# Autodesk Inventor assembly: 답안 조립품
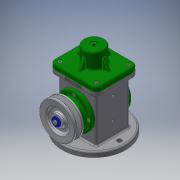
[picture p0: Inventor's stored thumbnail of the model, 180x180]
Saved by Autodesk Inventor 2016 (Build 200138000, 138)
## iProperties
Created: 2018-10
Part Number: 답안 조립품
Material: 일반
Document SubType Name: Assembly
Designer: USER
Author: USER
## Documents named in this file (18)
- C:\Users\USER\Desktop\481007V1044\답안 조립품.iam
- C:\Users\USER\Desktop\481007V1044\본체.ipt
- C:\Users\USER\Desktop\481007V1044\E-링.ipt
- C:\Users\USER\Desktop\481007V1044\V-벨트풀리.ipt
- C:\Users\USER\Desktop\481007V1044\덮개.ipt
- C:\Users\USER\Desktop\481007V1044\뒤커버.ipt
- C:\Users\USER\Desktop\481007V1044\링크.ipt
- C:\Users\USER\Desktop\481007V1044\베어링 17 x 40 x 12.ipt
- C:\Users\USER\Desktop\481007V1044\볼트 M4 x 8.ipt
- C:\Users\USER\Desktop\481007V1044\볼트 M4 x 10.ipt
- C:\Users\USER\Desktop\481007V1044\슬라이더.ipt
- C:\Users\USER\Desktop\481007V1044\앞커버.ipt
- C:\Users\USER\Desktop\481007V1044\오일 실 17 30 8.ipt
- C:\Users\USER\Desktop\481007V1044\와셔 4x16.ipt
- C:\Users\USER\Desktop\481007V1044\클레비스 핀 6 x 22.ipt
- 클레비스 핀 6 x 22.ipt
- C:\Users\USER\Desktop\481007V1044\키 4 x 4 x 12.ipt
- C:\Users\USER\Desktop\481007V1044\편심축.ipt
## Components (2 placed, 2 different names)
1. E-링:1
2. V-벨트풀리:1
## Component patterns: 구성요소 패턴 1:2 (2 elements)
